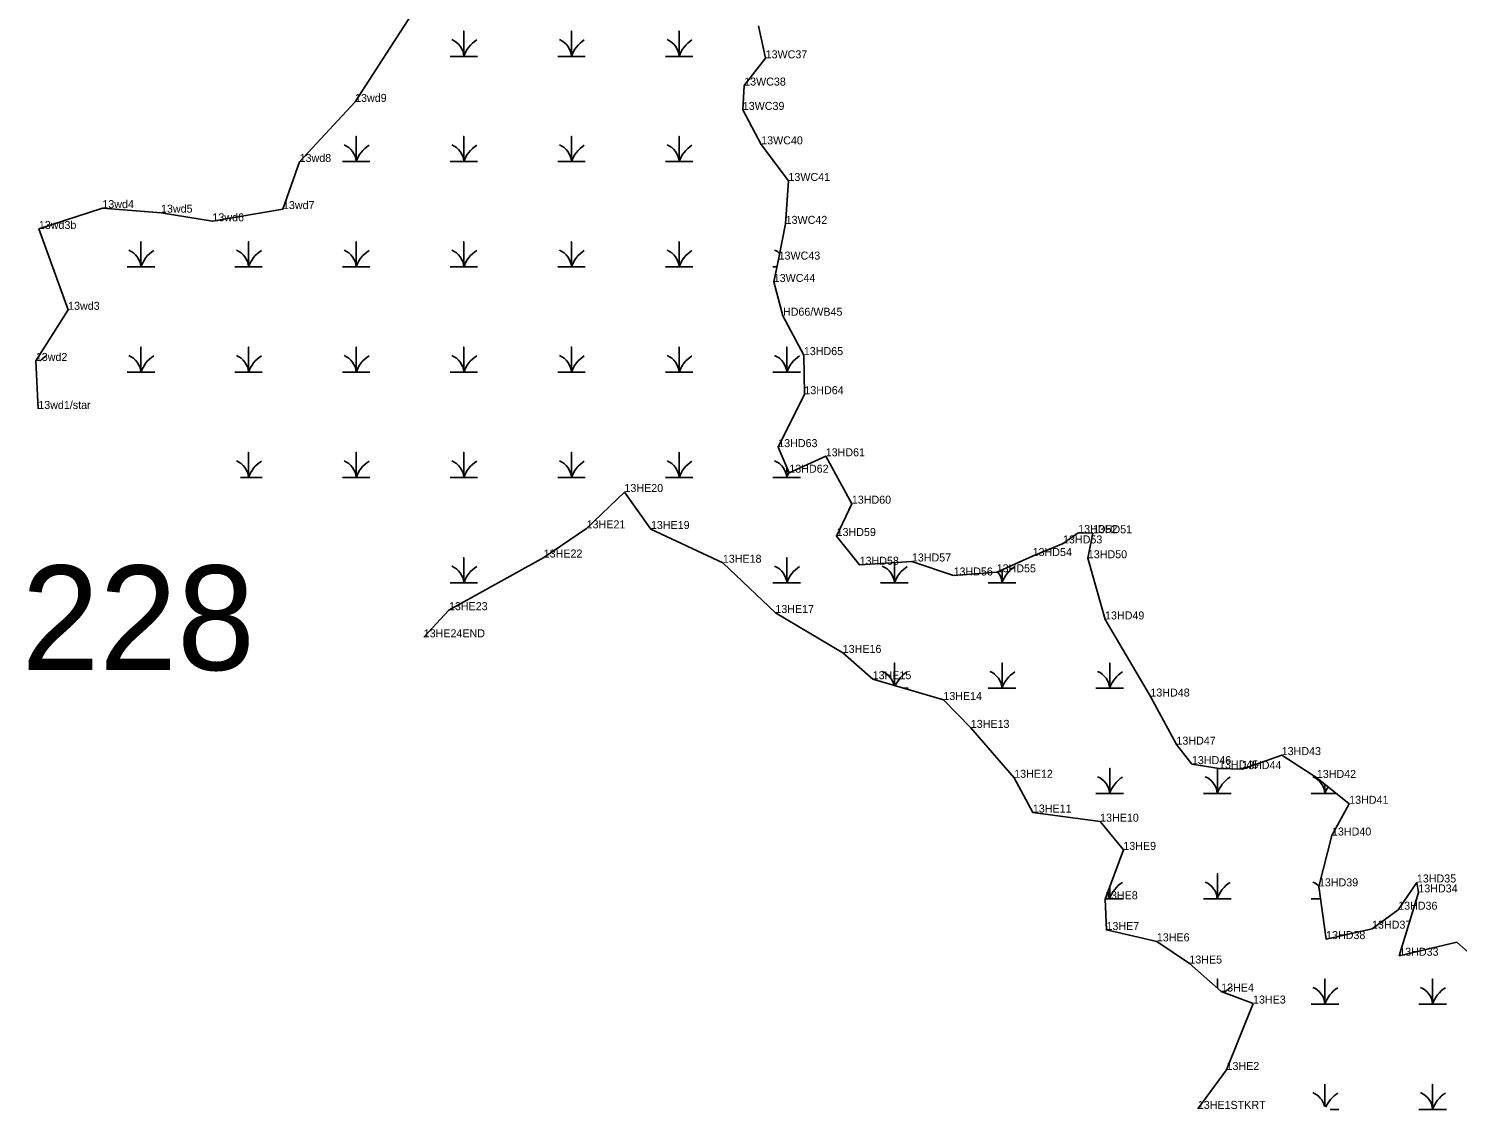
# Model space of a CAD drawing. Extents: x 2072529 to 2268796, y 436423 to 470397.
# Drawn here: x 2249869 to 2250761, y 444703 to 445378 of the extents above; entities that cross this region are included whole.
import ezdxf

# ---------------------------------------------------------------- set-up
doc = ezdxf.new("R2010")
doc.units = 0
for name, color, linetype in [('Default', 7, 'Continuous'), ('Exist Environmental Wetland Boundary', 7, 'Continuous'), ('Exist Environmental Wetland Boundary Cogo Comment', 7, 'Continuous'), ('Exist Environmental Wetland Boundary Cogo Point CELL', 7, 'Continuous'), ('Exist Hydro Swamp or Marsh', 7, 'Continuous')]:
    doc.layers.add(name, color=color, linetype=linetype)

msp = doc.modelspace()

# ---------------------------------------------------------------- linework, layer by layer
at = {"layer": 'Exist Environmental Wetland Boundary'}
for points in [[(2249874.87, 445140.64), (2249873.34, 445170.62), (2249893.51, 445202.55), (2249875.24, 445253.08), (2249914.9, 445266.09), (2249951.57, 445263.26), (2249983.69, 445257.87), (2250027.76, 445265.5), (2250038.16, 445294.96), (2250072.8, 445332.47), (2250109.77, 445389.59)], [(2250324.88, 445379.93), (2250329.29, 445359.7), (2250315.88, 445342.67), (2250315.01, 445327.47), (2250326.51, 445305.95), (2250343.54, 445283.07), (2250341.79, 445256.26), (2250337.38, 445233.94), (2250334.35, 445219.96), (2250340.12, 445198.86), (2250353.16, 445174.26), (2250353.5, 445149.85), (2250337.16, 445116.76), (2250344.09, 445100.78), (2250366.82, 445111.04), (2250383.14, 445081.42), (2250373.64, 445061.21), (2250388.02, 445043.24), (2250420.65, 445045.31), (2250446.71, 445036.56), (2250473.65, 445038.55), (2250496.09, 445048.71), (2250515.09, 445056.59), (2250524.53, 445063.13), (2250533.7, 445062.95), (2250530.58, 445047.32), (2250541.35, 445009.11), (2250569.67, 444960.92)], [(2250599.3, 444703.26), (2250617.23, 444727.59), (2250633.79, 444769.1), (2250613.89, 444776.59), (2250594, 444794.08), (2250573.68, 444807.96), (2250542.23, 444815.05), (2250541.32, 444834.25), (2250552.77, 444865.11), (2250538.25, 444882.74), (2250496.23, 444888.43), (2250484.56, 444910.16), (2250457.45, 444941.33), (2250440.32, 444958.77), (2250396.17, 444971.73), (2250377.46, 444988.18), (2250335.36, 445013.14), (2250302.55, 445044.51), (2250257.63, 445065.59), (2250241.08, 445088.71), (2250217.48, 445066), (2250190.65, 445047.76), (2250131.45, 445014.89), (2250115.67, 444997.92)], [(2250569.67, 444960.92), (2250585.93, 444930.87), (2250595.62, 444918.67), (2250612.55, 444915.97), (2250626.97, 444915.57), (2250651.71, 444924.32), (2250673.66, 444910.05), (2250693.85, 444893.89), (2250683.12, 444874.09), (2250674.94, 444842.31), (2250679.43, 444809.37), (2250708.15, 444815.88), (2250724.47, 444827.73), (2250736.14, 444844.74), (2250737.08, 444838.53), (2250725.14, 444798.96), (2250761.04, 444807.39), (2250809.19, 444764.92), (2250847.9, 444738.99)]]:
    msp.add_lwpolyline(points, dxfattribs=at)
at = {"layer": 'Exist Environmental Wetland Boundary Cogo Point CELL'}
for p, q in [((2250329.29, 445359.7), (2250329.29, 445359.7)), ((2250315.88, 445342.67), (2250315.88, 445342.67)), ((2250072.8, 445332.47), (2250072.8, 445332.47)), ((2250315.01, 445327.47), (2250315.01, 445327.47)), ((2250326.51, 445305.95), (2250326.51, 445305.95)), ((2250038.16, 445294.96), (2250038.16, 445294.96)), ((2250343.54, 445283.07), (2250343.54, 445283.07)), ((2249914.9, 445266.09), (2249914.9, 445266.09)), ((2250027.76, 445265.5), (2250027.76, 445265.5)), ((2249951.57, 445263.26), (2249951.57, 445263.26)), ((2249983.69, 445257.87), (2249983.69, 445257.87)), ((2250341.79, 445256.26), (2250341.79, 445256.26)), ((2249875.24, 445253.08), (2249875.24, 445253.08)), ((2250337.38, 445233.94), (2250337.38, 445233.94)), ((2250334.35, 445219.96), (2250334.35, 445219.96)), ((2249893.51, 445202.55), (2249893.51, 445202.55)), ((2250340.12, 445198.86), (2250340.12, 445198.86)), ((2250353.16, 445174.26), (2250353.16, 445174.26)), ((2249873.34, 445170.62), (2249873.34, 445170.62)), ((2250353.5, 445149.85), (2250353.5, 445149.85)), ((2249874.87, 445140.64), (2249874.87, 445140.64)), ((2250337.16, 445116.76), (2250337.16, 445116.76)), ((2250366.82, 445111.04), (2250366.82, 445111.04)), ((2250344.09, 445100.78), (2250344.09, 445100.78)), ((2250241.08, 445088.71), (2250241.08, 445088.71)), ((2250383.14, 445081.42), (2250383.14, 445081.42)), ((2250217.48, 445066), (2250217.48, 445066)), ((2250257.63, 445065.59), (2250257.63, 445065.59)), ((2250373.64, 445061.21), (2250373.64, 445061.21)), ((2250524.53, 445063.13), (2250524.53, 445063.13)), ((2250533.7, 445062.95), (2250533.7, 445062.95)), ((2250515.09, 445056.59), (2250515.09, 445056.59)), ((2250190.65, 445047.76), (2250190.65, 445047.76)), ((2250302.55, 445044.51), (2250302.55, 445044.51)), ((2250388.02, 445043.24), (2250388.02, 445043.24)), ((2250420.65, 445045.31), (2250420.65, 445045.31)), ((2250496.09, 445048.71), (2250496.09, 445048.71)), ((2250530.58, 445047.32), (2250530.58, 445047.32)), ((2250446.71, 445036.56), (2250446.71, 445036.56)), ((2250473.65, 445038.55), (2250473.65, 445038.55)), ((2250131.45, 445014.89), (2250131.45, 445014.89)), ((2250335.36, 445013.14), (2250335.36, 445013.14)), ((2250541.35, 445009.11), (2250541.35, 445009.11)), ((2250115.67, 444997.92), (2250115.67, 444997.92)), ((2250377.46, 444988.18), (2250377.46, 444988.18)), ((2250396.17, 444971.73), (2250396.17, 444971.73)), ((2250569.67, 444960.92), (2250569.67, 444960.92)), ((2250440.32, 444958.77), (2250440.32, 444958.77)), ((2250457.45, 444941.33), (2250457.45, 444941.33)), ((2250585.93, 444930.87), (2250585.93, 444930.87)), ((2250651.71, 444924.32), (2250651.71, 444924.32)), ((2250595.62, 444918.67), (2250595.62, 444918.67)), ((2250612.55, 444915.97), (2250612.55, 444915.97)), ((2250626.97, 444915.57), (2250626.97, 444915.57)), ((2250484.56, 444910.16), (2250484.56, 444910.16)), ((2250673.66, 444910.05), (2250673.66, 444910.05)), ((2250693.85, 444893.89), (2250693.85, 444893.89)), ((2250496.23, 444888.43), (2250496.23, 444888.43)), ((2250538.25, 444882.74), (2250538.25, 444882.74)), ((2250683.12, 444874.09), (2250683.12, 444874.09)), ((2250552.77, 444865.11), (2250552.77, 444865.11)), ((2250736.14, 444844.74), (2250736.14, 444844.74)), ((2250674.94, 444842.31), (2250674.94, 444842.31)), ((2250737.08, 444838.53), (2250737.08, 444838.53)), ((2250541.32, 444834.25), (2250541.32, 444834.25)), ((2250724.47, 444827.73), (2250724.47, 444827.73)), ((2250542.23, 444815.05), (2250542.23, 444815.05)), ((2250679.43, 444809.37), (2250679.43, 444809.37)), ((2250708.15, 444815.88), (2250708.15, 444815.88)), ((2250573.68, 444807.96), (2250573.68, 444807.96)), ((2250761.04, 444807.39), (2250761.04, 444807.39)), ((2250594, 444794.08), (2250594, 444794.08)), ((2250725.14, 444798.96), (2250725.14, 444798.96)), ((2250613.89, 444776.59), (2250613.89, 444776.59)), ((2250633.79, 444769.1), (2250633.79, 444769.1)), ((2250617.23, 444727.59), (2250617.23, 444727.59)), ((2250599.3, 444703.26), (2250599.3, 444703.26))]:
    msp.add_line(p, q, dxfattribs=at)
at = {"layer": 'Exist Hydro Swamp or Marsh'}
for points in [[(2250132.14, 445360.94), (2250140.74, 445360.94), (2250140.74, 445376.72), (2250140.74, 445360.94), (2250149.34, 445360.94)], [(2250199.39, 445360.94), (2250207.99, 445360.94), (2250207.99, 445376.72), (2250207.99, 445360.94), (2250216.59, 445360.94)], [(2250266.64, 445360.94), (2250275.24, 445360.94), (2250275.24, 445376.72), (2250275.24, 445360.94), (2250283.84, 445360.94)], [(2250064.89, 445295.14), (2250073.49, 445295.14), (2250073.49, 445310.92), (2250073.49, 445295.14), (2250082.09, 445295.14)], [(2250132.14, 445295.14), (2250140.74, 445295.14), (2250140.74, 445310.92), (2250140.74, 445295.14), (2250149.34, 445295.14)], [(2250199.39, 445295.14), (2250207.99, 445295.14), (2250207.99, 445310.92), (2250207.99, 445295.14), (2250216.59, 445295.14)], [(2250266.64, 445295.14), (2250275.24, 445295.14), (2250275.24, 445310.92), (2250275.24, 445295.14), (2250283.84, 445295.14)], [(2250333.89, 445295.14), (2250334.56, 445295.14)], [(2249930.39, 445229.34), (2249938.99, 445229.34), (2249938.99, 445245.12), (2249938.99, 445229.34), (2249947.59, 445229.34)], [(2249997.64, 445229.34), (2250006.24, 445229.34), (2250006.24, 445245.12), (2250006.24, 445229.34), (2250014.84, 445229.34)], [(2250064.89, 445229.34), (2250073.49, 445229.34), (2250073.49, 445245.12), (2250073.49, 445229.34), (2250082.09, 445229.34)], [(2250132.14, 445229.34), (2250140.74, 445229.34), (2250140.74, 445245.12), (2250140.74, 445229.34), (2250149.34, 445229.34)], [(2250199.39, 445229.34), (2250207.99, 445229.34), (2250207.99, 445245.12), (2250207.99, 445229.34), (2250216.59, 445229.34)], [(2250266.64, 445229.34), (2250275.24, 445229.34), (2250275.24, 445245.12), (2250275.24, 445229.34), (2250283.84, 445229.34)], [(2250333.89, 445229.34), (2250336.38, 445229.34)], [(2249930.39, 445163.54), (2249938.99, 445163.54), (2249938.99, 445179.32), (2249938.99, 445163.54), (2249947.59, 445163.54)], [(2249997.64, 445163.54), (2250006.24, 445163.54), (2250006.24, 445179.32), (2250006.24, 445163.54), (2250014.84, 445163.54)], [(2250064.89, 445163.54), (2250073.49, 445163.54), (2250073.49, 445179.32), (2250073.49, 445163.54), (2250082.09, 445163.54)], [(2250132.14, 445163.54), (2250140.74, 445163.54), (2250140.74, 445179.32), (2250140.74, 445163.54), (2250149.34, 445163.54)], [(2250199.39, 445163.54), (2250207.99, 445163.54), (2250207.99, 445179.32), (2250207.99, 445163.54), (2250216.59, 445163.54)], [(2250266.64, 445163.54), (2250275.24, 445163.54), (2250275.24, 445179.32), (2250275.24, 445163.54), (2250283.84, 445163.54)], [(2250333.89, 445163.54), (2250342.49, 445163.54), (2250342.49, 445179.32), (2250342.49, 445163.54), (2250351.09, 445163.54)], [(2250001.22, 445097.74), (2250006.24, 445097.74), (2250006.24, 445113.52), (2250006.24, 445097.74), (2250014.84, 445097.74)], [(2250064.89, 445097.74), (2250073.49, 445097.74), (2250073.49, 445113.52), (2250073.49, 445097.74), (2250082.09, 445097.74)], [(2250132.14, 445097.74), (2250140.74, 445097.74), (2250140.74, 445113.52), (2250140.74, 445097.74), (2250149.34, 445097.74)], [(2250199.39, 445097.74), (2250207.99, 445097.74), (2250207.99, 445113.52), (2250207.99, 445097.74), (2250216.59, 445097.74)], [(2250266.64, 445097.74), (2250275.24, 445097.74), (2250275.24, 445113.52), (2250275.24, 445097.74), (2250283.84, 445097.74)], [(2250333.89, 445097.74), (2250342.49, 445097.74), (2250342.49, 445104.46)], [(2250342.49, 445104.46), (2250342.49, 445097.74), (2250351.09, 445097.74)], [(2250132.14, 445031.94), (2250140.74, 445031.94), (2250140.74, 445047.72), (2250140.74, 445031.94), (2250149.34, 445031.94)], [(2250333.89, 445031.94), (2250342.49, 445031.94), (2250342.49, 445047.72), (2250342.49, 445031.94), (2250351.09, 445031.94)], [(2250401.14, 445031.94), (2250409.74, 445031.94), (2250409.74, 445044.62)], [(2250409.74, 445044.62), (2250409.74, 445031.94), (2250418.34, 445031.94)], [(2250468.39, 445031.94), (2250476.99, 445031.94), (2250476.99, 445040.07)], [(2250476.99, 445040.07), (2250476.99, 445031.94), (2250485.59, 445031.94)], [(2250409.74, 444967.74), (2250409.74, 444981.92), (2250409.74, 444967.74)], [(2250468.39, 444966.14), (2250476.99, 444966.14), (2250476.99, 444981.92), (2250476.99, 444966.14), (2250485.59, 444966.14)], [(2250535.64, 444966.14), (2250544.24, 444966.14), (2250544.24, 444981.92), (2250544.24, 444966.14), (2250552.84, 444966.14)], [(2250415.21, 444966.14), (2250418.34, 444966.14)], [(2250535.64, 444900.34), (2250544.24, 444900.34), (2250544.24, 444916.12), (2250544.24, 444900.34), (2250552.84, 444900.34)], [(2250602.89, 444900.34), (2250611.49, 444900.34), (2250611.49, 444916.12), (2250611.49, 444900.34), (2250620.09, 444900.34)], [(2250670.14, 444900.34), (2250678.74, 444900.34), (2250678.74, 444905.98)], [(2250678.74, 444905.98), (2250678.74, 444900.34), (2250685.79, 444900.34)], [(2250602.89, 444834.54), (2250611.49, 444834.54), (2250611.49, 444850.32), (2250611.49, 444834.54), (2250620.09, 444834.54)], [(2250541.43, 444834.54), (2250544.24, 444834.54), (2250544.24, 444842.11)], [(2250544.24, 444842.11), (2250544.24, 444834.54), (2250552.84, 444834.54)], [(2250670.14, 444834.54), (2250676, 444834.54)], [(2250611.49, 444778.7), (2250611.49, 444784.52), (2250611.49, 444778.7)], [(2250670.14, 444768.74), (2250678.74, 444768.74), (2250678.74, 444784.52), (2250678.74, 444768.74), (2250687.34, 444768.74)], [(2250737.39, 444768.74), (2250745.99, 444768.74), (2250745.99, 444784.52), (2250745.99, 444768.74), (2250754.59, 444768.74)], [(2250678.74, 444704.76), (2250678.74, 444718.72), (2250678.74, 444704.76)], [(2250737.39, 444702.94), (2250745.99, 444702.94), (2250745.99, 444718.72), (2250745.99, 444702.94), (2250754.59, 444702.94)], [(2250681.88, 444702.94), (2250687.34, 444702.94)]]:
    msp.add_lwpolyline(points, dxfattribs=at)
for centre, radius, start, end in [((2250128.47, 445360.05), 12.3, 4.14034, 67.53497), ((2250158.98, 445354.88), 19.22, 122.12745, 161.62219), ((2250195.72, 445360.05), 12.3, 4.14034, 67.53497), ((2250226.23, 445354.88), 19.22, 122.12745, 161.62219), ((2250262.97, 445360.05), 12.3, 4.14034, 67.53497), ((2250293.48, 445354.88), 19.22, 122.12745, 161.62219), ((2250061.22, 445294.25), 12.3, 4.14034, 67.53497), ((2250091.73, 445289.08), 19.22, 122.12745, 161.62219), ((2250128.47, 445294.25), 12.3, 4.14034, 67.53497), ((2250158.98, 445289.08), 19.22, 122.12745, 161.62219), ((2250195.72, 445294.25), 12.3, 4.14034, 67.53497), ((2250226.23, 445289.08), 19.22, 122.12745, 161.62219), ((2250262.97, 445294.25), 12.3, 4.14034, 67.53497), ((2250293.48, 445289.08), 19.22, 122.12745, 161.62219), ((2249926.72, 445228.45), 12.3, 4.14034, 67.53497), ((2249957.23, 445223.28), 19.22, 122.12745, 161.62219), ((2249993.97, 445228.45), 12.3, 4.14034, 67.53497), ((2250024.48, 445223.28), 19.22, 122.12745, 161.62219), ((2250061.22, 445228.45), 12.3, 4.14034, 67.53497), ((2250091.73, 445223.28), 19.22, 122.12745, 161.62219), ((2250128.47, 445228.45), 12.3, 4.14034, 67.53497), ((2250158.98, 445223.28), 19.22, 122.12745, 161.62219), ((2250195.72, 445228.45), 12.3, 4.14034, 67.53497), ((2250226.23, 445223.28), 19.22, 122.12745, 161.62219), ((2250262.97, 445228.45), 12.3, 4.14034, 67.53497), ((2250293.48, 445223.28), 19.22, 122.12745, 161.62219), ((2250330.22, 445228.45), 12.3, 49.84537, 67.53497), ((2249889.98, 445157.48), 19.22, 122.12745, 137.4658), ((2249926.72, 445162.65), 12.3, 4.14034, 67.53497), ((2249957.23, 445157.48), 19.22, 122.12745, 161.62219), ((2249993.97, 445162.65), 12.3, 4.14034, 67.53497), ((2250024.48, 445157.48), 19.22, 122.12745, 161.62219), ((2250061.22, 445162.65), 12.3, 4.14034, 67.53497), ((2250091.73, 445157.48), 19.22, 122.12745, 161.62219), ((2250128.47, 445162.65), 12.3, 4.14034, 67.53497), ((2250158.98, 445157.48), 19.22, 122.12745, 161.62219), ((2250195.72, 445162.65), 12.3, 4.14034, 67.53497), ((2250226.23, 445157.48), 19.22, 122.12745, 161.62219), ((2250262.97, 445162.65), 12.3, 4.14034, 67.53497), ((2250293.48, 445157.48), 19.22, 122.12745, 161.62219), ((2250330.22, 445162.65), 12.3, 4.14034, 67.53497), ((2250360.73, 445157.48), 19.22, 122.12745, 161.62219), ((2249993.97, 445096.85), 12.3, 4.14034, 67.53497), ((2250024.48, 445091.68), 19.22, 122.12745, 161.62219), ((2250061.22, 445096.85), 12.3, 4.14034, 67.53497), ((2250091.73, 445091.68), 19.22, 122.12745, 161.62219), ((2250128.47, 445096.85), 12.3, 4.14034, 67.53497), ((2250158.98, 445091.68), 19.22, 122.12745, 161.62219), ((2250195.72, 445096.85), 12.3, 4.14034, 67.53497), ((2250226.23, 445091.68), 19.22, 122.12745, 161.62219), ((2250262.97, 445096.85), 12.3, 4.14034, 67.53497), ((2250293.48, 445091.68), 19.22, 122.12745, 161.62219), ((2250330.22, 445096.85), 12.3, 4.14034, 67.53497), ((2250360.73, 445091.68), 19.22, 150.75087, 161.62219), ((2250128.47, 445031.05), 12.3, 4.14034, 67.53497), ((2250158.98, 445025.88), 19.22, 122.12745, 161.62219), ((2250330.22, 445031.05), 12.3, 4.14034, 67.53497), ((2250360.73, 445025.88), 19.22, 122.12745, 161.62219), ((2250397.47, 445031.05), 12.3, 4.14034, 67.53497), ((2250427.98, 445025.88), 19.22, 122.12745, 161.62219), ((2250495.23, 445025.88), 19.22, 122.12745, 161.62219), ((2250464.72, 445031.05), 12.3, 4.14034, 39.22618), ((2250397.47, 444965.25), 12.3, 12.02773, 67.53497), ((2250427.98, 444960.08), 19.22, 122.12745, 157.01752), ((2250464.72, 444965.25), 12.3, 4.14034, 67.53497), ((2250495.23, 444960.08), 19.22, 122.12745, 161.62219), ((2250531.97, 444965.25), 12.3, 4.14034, 67.53497), ((2250562.48, 444960.08), 19.22, 122.12745, 161.62219), ((2250495.23, 444894.28), 19.22, 122.12745, 123.9356), ((2250531.97, 444899.45), 12.3, 4.14034, 67.53497), ((2250562.48, 444894.28), 19.22, 122.12745, 161.62219), ((2250599.22, 444899.45), 12.3, 4.14034, 67.53497), ((2250629.73, 444894.28), 19.22, 122.12745, 161.62219), ((2250666.47, 444899.45), 12.3, 4.14034, 67.53497), ((2250696.98, 444894.28), 19.22, 148.08916, 161.62219), ((2250562.48, 444828.48), 19.22, 122.12745, 161.62219), ((2250599.22, 444833.65), 12.3, 4.14034, 67.53497), ((2250629.73, 444828.48), 19.22, 122.12745, 161.62219), ((2250666.47, 444833.65), 12.3, 46.16028, 67.53497), ((2250531.97, 444833.65), 12.3, 4.14034, 25.54858), ((2250629.73, 444762.68), 19.22, 122.12745, 136.59245), ((2250666.47, 444767.85), 12.3, 4.14034, 67.53497), ((2250696.98, 444762.68), 19.22, 122.12745, 161.62219), ((2250733.72, 444767.85), 12.3, 4.14034, 67.53497), ((2250764.23, 444762.68), 19.22, 122.12745, 161.62219), ((2250666.47, 444702.05), 12.3, 13.58141, 67.53497), ((2250696.98, 444696.88), 19.22, 122.12745, 156.86706), ((2250733.72, 444702.05), 12.3, 4.14034, 67.53497), ((2250764.23, 444696.88), 19.22, 122.12745, 161.62219)]:
    msp.add_arc(centre, radius, start, end, dxfattribs=at)

# ---------------------------------------------------------------- texts
at = {"layer": 'Default'}
msp.add_text('228', height=65.34, dxfattribs=at).set_placement((2249864.42, 444977.47))
at = {"layer": 'Exist Environmental Wetland Boundary Cogo Comment'}
for s, p in [('13WC37', (2250329.29, 445359.7)), ('13WC38', (2250315.88, 445342.67)), ('13wd9', (2250072.8, 445332.47)), ('13WC39', (2250315.01, 445327.47)), ('13WC40', (2250326.51, 445305.95)), ('13wd8', (2250038.16, 445294.96)), ('13WC41', (2250343.54, 445283.07)), ('13wd4', (2249914.9, 445266.09)), ('13wd5', (2249951.57, 445263.26)), ('13wd7', (2250027.76, 445265.5)), ('13wd3b', (2249875.24, 445253.08)), ('13wd6', (2249983.69, 445257.87)), ('13WC42', (2250341.79, 445256.26)), ('13WC43', (2250337.38, 445233.94)), ('13WC44', (2250334.35, 445219.96)), ('13wd3', (2249893.51, 445202.55)), ('HD66/WB45', (2250340.12, 445198.86)), ('13wd2', (2249873.34, 445170.62)), ('13HD65', (2250353.16, 445174.26)), ('13HD64', (2250353.5, 445149.85)), ('13wd1/star', (2249874.87, 445140.64)), ('13HD63', (2250337.16, 445116.76)), ('13HD61', (2250366.82, 445111.04)), ('13HD62', (2250344.09, 445100.78)), ('13HE20', (2250241.08, 445088.71)), ('13HD60', (2250383.14, 445081.42)), ('13HE21', (2250217.48, 445066)), ('13HE19', (2250257.63, 445065.59)), ('13HD52', (2250524.53, 445063.13)), ('13HD51', (2250533.7, 445062.95)), ('13HD59', (2250373.64, 445061.21)), ('13HD53', (2250515.09, 445056.59)), ('13HE22', (2250190.65, 445047.76)), ('13HE18', (2250302.55, 445044.51)), ('13HD57', (2250420.65, 445045.31)), ('13HD54', (2250496.09, 445048.71)), ('13HD50', (2250530.58, 445047.32)), ('13HD58', (2250388.02, 445043.24)), ('13HD56', (2250446.71, 445036.56)), ('13HD55', (2250473.65, 445038.55)), ('13HE23', (2250131.45, 445014.89)), ('13HE17', (2250335.36, 445013.14)), ('13HD49', (2250541.35, 445009.11)), ('13HE24END', (2250115.67, 444997.92)), ('13HE16', (2250377.46, 444988.18)), ('13HE15', (2250396.17, 444971.73)), ('13HE14', (2250440.32, 444958.77)), ('13HD48', (2250569.67, 444960.92)), ('13HE13', (2250457.45, 444941.33)), ('13HD47', (2250585.93, 444930.87)), ('13HD43', (2250651.71, 444924.32)), ('13HD46', (2250595.62, 444918.67)), ('13HD45', (2250612.55, 444915.97)), ('13HD44', (2250626.97, 444915.57)), ('13HE12', (2250484.56, 444910.16)), ('13HD42', (2250673.66, 444910.05)), ('13HD41', (2250693.85, 444893.89)), ('13HE11', (2250496.23, 444888.43)), ('13HE10', (2250538.25, 444882.74)), ('13HD40', (2250683.12, 444874.09)), ('13HE9', (2250552.77, 444865.11)), ('13HD39', (2250674.94, 444842.31)), ('13HD35', (2250736.14, 444844.74)), ('13HE8', (2250541.32, 444834.25)), ('13HD34', (2250737.08, 444838.53)), ('13HD36', (2250724.47, 444827.73)), ('13HE7', (2250542.23, 444815.05)), ('13HD37', (2250708.15, 444815.88)), ('13HE6', (2250573.68, 444807.96)), ('13HD38', (2250679.43, 444809.37)), ('13HD33', (2250725.14, 444798.96)), ('13HE5', (2250594, 444794.08)), ('13HE4', (2250613.89, 444776.59)), ('13HE3', (2250633.79, 444769.1)), ('13HE2', (2250617.23, 444727.59)), ('13HE1STKRT', (2250599.3, 444703.26))]:
    msp.add_text(s, height=5, dxfattribs=at).set_placement(p)

doc.saveas('drawing.dxf')
